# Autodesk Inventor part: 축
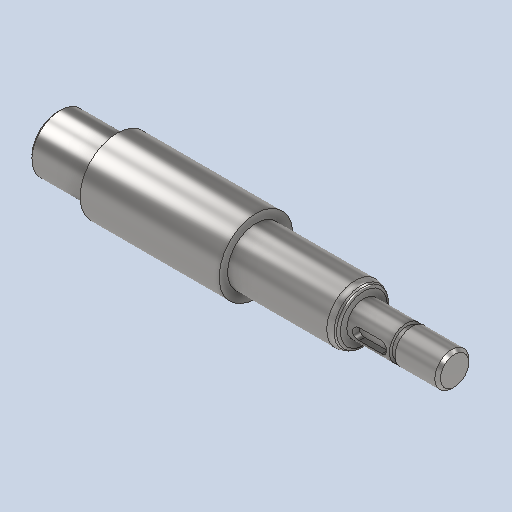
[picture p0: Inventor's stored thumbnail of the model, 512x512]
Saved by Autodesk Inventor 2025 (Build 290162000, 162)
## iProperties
Created: 2024-08
Part Number: 축
Material: 강철, 연강
Document SubType Name: Modeling
Designer: 학생
Density: 7.86 g/cm^3
Appearance: 기본값
Author: jhkim
Sending System: Autodesk Inventor 2025
Preprocessor: ST-DEVELOPER v20
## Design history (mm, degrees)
feature "솔리드2"
node "솔리드1"
